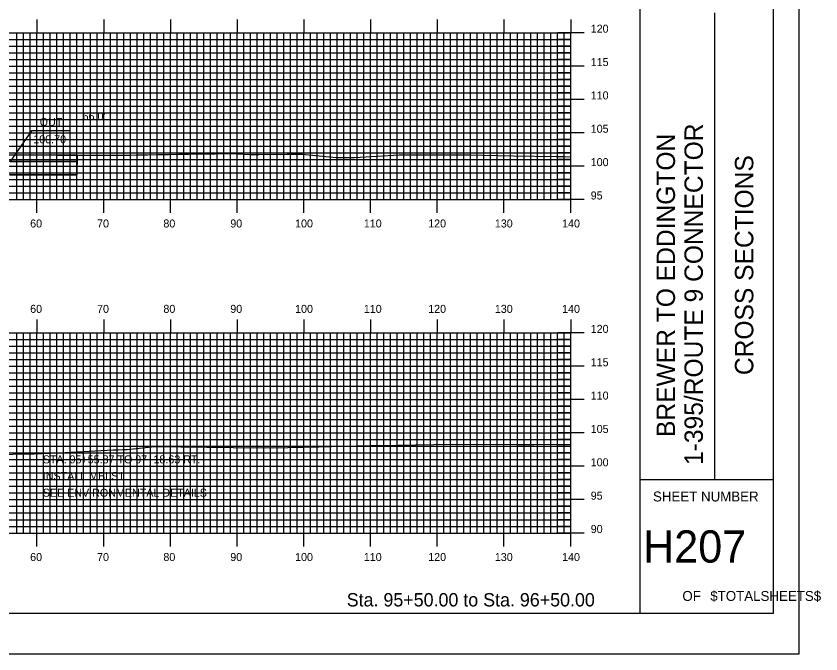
# Model space of a CAD drawing. Extents: x 1765726 to 1766069, y 442591 to 442811.
# Drawn here: x 1765948.8 to 1766069.4, y 442590.5 to 442686.2 of the extents above; entities that cross this region are included whole.
import ezdxf

# ---------------------------------------------------------------- set-up
doc = ezdxf.new("R2010")
doc.units = 0
for name, color, linetype in [('ANNOTATION', 7, 'Continuous'), ('BORDER', 7, 'Continuous'), ('D_Roadway_FinishedGrade', 7, 'Continuous'), ('D_Roadway_SlopeLines', 7, 'Continuous'), ('D_Text_Standard', 7, 'Continuous'), ('H_V ANNOTATION', 7, 'Continuous'), ('MAJOR', 7, 'Continuous'), ('MINOR', 7, 'Continuous'), ('PLOT BOUNDARY', 7, 'Continuous'), ('S_Roadway_Centerline', 7, 'Continuous')]:
    doc.layers.add(name, color=color, linetype=linetype)

msp = doc.modelspace()

# ---------------------------------------------------------------- linework, layer by layer
at = {"layer": 'ANNOTATION'}
msp.add_lwpolyline([(1765956.74, 442668.96), (1765951.05, 442668.96), (1765947.87, 442664.37)], dxfattribs=at)
at = {"layer": 'BORDER'}
for p, q in [((1766042.28, 442596.67), (1766042.28, 442806.67)), ((1766053.47, 442616.67), (1766053.47, 442686.67)), ((1766042.28, 442616.67), (1766062.28, 442616.67))]:
    msp.add_line(p, q, dxfattribs=at)
msp.add_lwpolyline([(1765742.28, 442596.67), (1766062.28, 442596.67), (1766062.28, 442806.67), (1765742.28, 442806.67)], close=True, dxfattribs=at)
at = {"layer": 'D_Roadway_FinishedGrade'}
for p, q in [((1765957.89, 442665.34), (1765957.88, 442662.37)), ((1765947.87, 442664.37), (1765957.88, 442664.37)), ((1765957.88, 442662.37), (1765947.87, 442662.37))]:
    msp.add_line(p, q, dxfattribs=at)
msp.add_lwpolyline([(1765931.99, 442670.4), (1765931.99, 442668.4), (1765947.87, 442662.37), (1765957.88, 442662.37), (1765957.88, 442664.37), (1765947.87, 442664.37)], close=True, dxfattribs=at)
at = {"layer": 'D_Roadway_SlopeLines'}
msp.add_lwpolyline([(1765947.88, 442665.37), (1765957.89, 442665.34)], dxfattribs=at)
at = {"layer": 'MAJOR'}
for p, q in [((1765951.88, 442685.67), (1765951.88, 442683.67)), ((1765961.88, 442685.67), (1765961.88, 442683.67)), ((1765971.88, 442685.67), (1765971.88, 442683.67)), ((1765981.88, 442685.67), (1765981.88, 442683.67)), ((1765991.88, 442685.67), (1765991.88, 442683.67)), ((1766001.88, 442685.67), (1766001.88, 442683.67)), ((1766011.88, 442685.67), (1766011.88, 442683.67)), ((1766021.88, 442685.67), (1766021.88, 442683.67)), ((1766031.88, 442685.67), (1766031.88, 442683.67)), ((1765751.88, 442683.67), (1766031.88, 442683.67)), ((1765751.88, 442683.67), (1766031.88, 442683.67)), ((1765951.88, 442658.67), (1765951.88, 442683.67)), ((1765961.88, 442658.67), (1765961.88, 442683.67)), ((1765971.88, 442658.67), (1765971.88, 442683.67)), ((1765981.88, 442658.67), (1765981.88, 442683.67)), ((1765991.88, 442658.67), (1765991.88, 442683.67)), ((1766001.88, 442658.67), (1766001.88, 442683.67)), ((1766011.88, 442658.67), (1766011.88, 442683.67)), ((1766021.88, 442658.67), (1766021.88, 442683.67)), ((1766033.89, 442683.67), (1766029.88, 442683.67)), ((1766031.88, 442658.67), (1766031.88, 442683.67)), ((1766031.88, 442658.67), (1766031.88, 442683.67)), ((1765751.88, 442678.67), (1766031.88, 442678.67)), ((1766033.89, 442678.67), (1766029.88, 442678.67)), ((1765751.88, 442673.67), (1766031.88, 442673.67)), ((1766033.89, 442673.67), (1766029.88, 442673.67)), ((1765751.88, 442668.67), (1766031.88, 442668.67)), ((1766033.89, 442668.67), (1766029.88, 442668.67)), ((1765751.88, 442663.67), (1766031.88, 442663.67)), ((1766033.89, 442663.67), (1766029.88, 442663.67)), ((1765751.88, 442658.67), (1766031.88, 442658.67)), ((1765751.88, 442658.67), (1766031.88, 442658.67)), ((1765951.88, 442656.66), (1765951.88, 442658.67)), ((1765961.88, 442656.66), (1765961.88, 442658.67)), ((1765971.88, 442656.66), (1765971.88, 442658.67)), ((1765981.88, 442656.66), (1765981.88, 442658.67)), ((1765991.88, 442656.66), (1765991.88, 442658.67)), ((1766001.88, 442656.66), (1766001.88, 442658.67)), ((1766011.88, 442656.66), (1766011.88, 442658.67)), ((1766021.88, 442656.66), (1766021.88, 442658.67)), ((1766033.89, 442658.67), (1766029.88, 442658.67)), ((1766031.88, 442656.66), (1766031.88, 442658.67)), ((1765951.88, 442640.67), (1765951.88, 442638.67)), ((1765961.88, 442640.67), (1765961.88, 442638.67)), ((1765971.88, 442640.67), (1765971.88, 442638.67)), ((1765981.88, 442640.67), (1765981.88, 442638.67)), ((1765991.88, 442640.67), (1765991.88, 442638.67)), ((1766001.88, 442640.67), (1766001.88, 442638.67)), ((1766011.88, 442640.67), (1766011.88, 442638.67)), ((1766021.88, 442640.67), (1766021.88, 442638.67)), ((1766031.88, 442640.67), (1766031.88, 442638.67)), ((1765751.88, 442638.67), (1766031.88, 442638.67)), ((1765751.88, 442638.67), (1766031.88, 442638.67)), ((1765951.88, 442608.67), (1765951.88, 442638.67)), ((1765961.88, 442608.67), (1765961.88, 442638.67)), ((1765971.88, 442608.67), (1765971.88, 442638.67)), ((1765981.88, 442608.67), (1765981.88, 442638.67)), ((1765991.88, 442608.67), (1765991.88, 442638.67)), ((1766001.88, 442608.67), (1766001.88, 442638.67)), ((1766011.88, 442608.67), (1766011.88, 442638.67)), ((1766021.88, 442608.67), (1766021.88, 442638.67)), ((1766033.89, 442638.67), (1766029.88, 442638.67)), ((1766031.88, 442608.67), (1766031.88, 442638.67)), ((1766031.88, 442608.67), (1766031.88, 442638.67)), ((1765751.88, 442633.67), (1766031.88, 442633.67)), ((1766033.89, 442633.67), (1766029.88, 442633.67)), ((1765751.88, 442628.67), (1766031.88, 442628.67)), ((1766033.89, 442628.67), (1766029.88, 442628.67)), ((1765751.88, 442623.67), (1766031.88, 442623.67)), ((1766033.89, 442623.67), (1766029.88, 442623.67)), ((1765751.88, 442618.67), (1766031.88, 442618.67)), ((1766033.89, 442618.67), (1766029.88, 442618.67)), ((1765751.88, 442613.67), (1766031.88, 442613.67)), ((1766033.89, 442613.67), (1766029.88, 442613.67)), ((1765751.88, 442608.67), (1766031.88, 442608.67)), ((1765751.88, 442608.67), (1766031.88, 442608.67)), ((1765951.88, 442606.66), (1765951.88, 442608.67)), ((1765961.88, 442606.66), (1765961.88, 442608.67)), ((1765971.88, 442606.66), (1765971.88, 442608.67)), ((1765981.88, 442606.66), (1765981.88, 442608.67)), ((1765991.88, 442606.66), (1765991.88, 442608.67)), ((1766001.88, 442606.66), (1766001.88, 442608.67)), ((1766011.88, 442606.66), (1766011.88, 442608.67)), ((1766021.88, 442606.66), (1766021.88, 442608.67)), ((1766033.89, 442608.67), (1766029.88, 442608.67)), ((1766031.88, 442606.66), (1766031.88, 442608.67))]:
    msp.add_line(p, q, dxfattribs=at)
at = {"layer": 'MINOR'}
for p, q in [((1765751.88, 442682.67), (1766031.88, 442682.67)), ((1765948.88, 442658.67), (1765948.88, 442683.67)), ((1765949.88, 442658.67), (1765949.88, 442683.67)), ((1765950.88, 442658.67), (1765950.88, 442683.67)), ((1765952.88, 442658.67), (1765952.88, 442683.67)), ((1765953.88, 442658.67), (1765953.88, 442683.67)), ((1765954.88, 442658.67), (1765954.88, 442683.67)), ((1765955.88, 442658.67), (1765955.88, 442683.67)), ((1765956.88, 442658.67), (1765956.88, 442683.67)), ((1765957.88, 442658.67), (1765957.88, 442683.67)), ((1765958.88, 442658.67), (1765958.88, 442683.67)), ((1765959.88, 442658.67), (1765959.88, 442683.67)), ((1765960.88, 442658.67), (1765960.88, 442683.67)), ((1765962.88, 442658.67), (1765962.88, 442683.67)), ((1765963.88, 442658.67), (1765963.88, 442683.67)), ((1765964.88, 442658.67), (1765964.88, 442683.67)), ((1765965.88, 442658.67), (1765965.88, 442683.67)), ((1765966.88, 442658.67), (1765966.88, 442683.67)), ((1765967.88, 442658.67), (1765967.88, 442683.67)), ((1765968.88, 442658.67), (1765968.88, 442683.67)), ((1765969.88, 442658.67), (1765969.88, 442683.67)), ((1765970.88, 442658.67), (1765970.88, 442683.67)), ((1765972.88, 442658.67), (1765972.88, 442683.67)), ((1765973.88, 442658.67), (1765973.88, 442683.67)), ((1765974.88, 442658.67), (1765974.88, 442683.67)), ((1765975.88, 442658.67), (1765975.88, 442683.67)), ((1765976.88, 442658.67), (1765976.88, 442683.67)), ((1765977.88, 442658.67), (1765977.88, 442683.67)), ((1765978.88, 442658.67), (1765978.88, 442683.67)), ((1765979.88, 442658.67), (1765979.88, 442683.67)), ((1765980.88, 442658.67), (1765980.88, 442683.67)), ((1765982.88, 442658.67), (1765982.88, 442683.67)), ((1765983.88, 442658.67), (1765983.88, 442683.67)), ((1765984.88, 442658.67), (1765984.88, 442683.67)), ((1765985.88, 442658.67), (1765985.88, 442683.67)), ((1765986.88, 442658.67), (1765986.88, 442683.67)), ((1765987.88, 442658.67), (1765987.88, 442683.67)), ((1765988.88, 442658.67), (1765988.88, 442683.67)), ((1765989.88, 442658.67), (1765989.88, 442683.67)), ((1765990.88, 442658.67), (1765990.88, 442683.67)), ((1765992.88, 442658.67), (1765992.88, 442683.67)), ((1765993.88, 442658.67), (1765993.88, 442683.67)), ((1765994.88, 442658.67), (1765994.88, 442683.67)), ((1765995.88, 442658.67), (1765995.88, 442683.67)), ((1765996.88, 442658.67), (1765996.88, 442683.67)), ((1765997.88, 442658.67), (1765997.88, 442683.67)), ((1765998.88, 442658.67), (1765998.88, 442683.67)), ((1765999.88, 442658.67), (1765999.88, 442683.67)), ((1766000.88, 442658.67), (1766000.88, 442683.67)), ((1766002.88, 442658.67), (1766002.88, 442683.67)), ((1766003.88, 442658.67), (1766003.88, 442683.67)), ((1766004.88, 442658.67), (1766004.88, 442683.67)), ((1766005.88, 442658.67), (1766005.88, 442683.67)), ((1766006.88, 442658.67), (1766006.88, 442683.67)), ((1766007.88, 442658.67), (1766007.88, 442683.67)), ((1766008.88, 442658.67), (1766008.88, 442683.67)), ((1766009.88, 442658.67), (1766009.88, 442683.67)), ((1766010.88, 442658.67), (1766010.88, 442683.67)), ((1766012.88, 442658.67), (1766012.88, 442683.67)), ((1766013.88, 442658.67), (1766013.88, 442683.67)), ((1766014.88, 442658.67), (1766014.88, 442683.67)), ((1766015.88, 442658.67), (1766015.88, 442683.67)), ((1766016.88, 442658.67), (1766016.88, 442683.67)), ((1766017.88, 442658.67), (1766017.88, 442683.67)), ((1766018.88, 442658.67), (1766018.88, 442683.67)), ((1766019.88, 442658.67), (1766019.88, 442683.67)), ((1766020.88, 442658.67), (1766020.88, 442683.67)), ((1766022.88, 442658.67), (1766022.88, 442683.67)), ((1766023.88, 442658.67), (1766023.88, 442683.67)), ((1766024.88, 442658.67), (1766024.88, 442683.67)), ((1766025.88, 442658.67), (1766025.88, 442683.67)), ((1766026.88, 442658.67), (1766026.88, 442683.67)), ((1766027.88, 442658.67), (1766027.88, 442683.67)), ((1766028.88, 442658.67), (1766028.88, 442683.67)), ((1766029.88, 442658.67), (1766029.88, 442683.67)), ((1766031.88, 442682.67), (1766029.88, 442682.67)), ((1766030.88, 442658.67), (1766030.88, 442683.67)), ((1765751.88, 442681.67), (1766031.88, 442681.67)), ((1766031.88, 442681.67), (1766029.88, 442681.67)), ((1765751.88, 442680.67), (1766031.88, 442680.67)), ((1766031.88, 442680.67), (1766029.88, 442680.67)), ((1765751.88, 442679.67), (1766031.88, 442679.67)), ((1766031.88, 442679.67), (1766029.88, 442679.67)), ((1765751.88, 442677.67), (1766031.88, 442677.67)), ((1765751.88, 442676.67), (1766031.88, 442676.67)), ((1766031.88, 442677.67), (1766029.88, 442677.67)), ((1766031.88, 442676.67), (1766029.88, 442676.67)), ((1765751.88, 442675.67), (1766031.88, 442675.67)), ((1766031.88, 442675.67), (1766029.88, 442675.67)), ((1765751.88, 442674.67), (1766031.88, 442674.67)), ((1766031.88, 442674.67), (1766029.88, 442674.67)), ((1765751.88, 442672.67), (1766031.88, 442672.67)), ((1766031.88, 442672.67), (1766029.88, 442672.67)), ((1765751.88, 442671.67), (1766031.88, 442671.67)), ((1765751.88, 442670.67), (1766031.88, 442670.67)), ((1766031.88, 442671.67), (1766029.88, 442671.67)), ((1766031.88, 442670.67), (1766029.88, 442670.67)), ((1765751.88, 442669.67), (1766031.88, 442669.67)), ((1766031.88, 442669.67), (1766029.88, 442669.67)), ((1765751.88, 442667.67), (1766031.88, 442667.67)), ((1766031.88, 442667.67), (1766029.88, 442667.67)), ((1765751.88, 442666.67), (1766031.88, 442666.67)), ((1766031.88, 442666.67), (1766029.88, 442666.67)), ((1765751.88, 442665.67), (1766031.88, 442665.67)), ((1765751.88, 442664.67), (1766031.88, 442664.67)), ((1766031.88, 442665.67), (1766029.88, 442665.67)), ((1766031.88, 442664.67), (1766029.88, 442664.67)), ((1765751.88, 442662.67), (1766031.88, 442662.67)), ((1766031.88, 442662.67), (1766029.88, 442662.67)), ((1765751.88, 442661.67), (1766031.88, 442661.67)), ((1766031.88, 442661.67), (1766029.88, 442661.67)), ((1765751.88, 442660.67), (1766031.88, 442660.67)), ((1766031.88, 442660.67), (1766029.88, 442660.67)), ((1765751.88, 442659.67), (1766031.88, 442659.67)), ((1766031.88, 442659.67), (1766029.88, 442659.67)), ((1765948.88, 442608.67), (1765948.88, 442638.67)), ((1765949.88, 442608.67), (1765949.88, 442638.67)), ((1765950.88, 442608.67), (1765950.88, 442638.67)), ((1765952.88, 442608.67), (1765952.88, 442638.67)), ((1765953.88, 442608.67), (1765953.88, 442638.67)), ((1765954.88, 442608.67), (1765954.88, 442638.67)), ((1765955.88, 442608.67), (1765955.88, 442638.67)), ((1765956.88, 442608.67), (1765956.88, 442638.67)), ((1765957.88, 442608.67), (1765957.88, 442638.67)), ((1765958.88, 442608.67), (1765958.88, 442638.67)), ((1765959.88, 442608.67), (1765959.88, 442638.67)), ((1765960.88, 442608.67), (1765960.88, 442638.67)), ((1765962.88, 442608.67), (1765962.88, 442638.67)), ((1765963.88, 442608.67), (1765963.88, 442638.67)), ((1765964.88, 442608.67), (1765964.88, 442638.67)), ((1765965.88, 442608.67), (1765965.88, 442638.67)), ((1765966.88, 442608.67), (1765966.88, 442638.67)), ((1765967.88, 442608.67), (1765967.88, 442638.67)), ((1765968.88, 442608.67), (1765968.88, 442638.67)), ((1765969.88, 442608.67), (1765969.88, 442638.67)), ((1765970.88, 442608.67), (1765970.88, 442638.67)), ((1765972.88, 442608.67), (1765972.88, 442638.67)), ((1765973.88, 442608.67), (1765973.88, 442638.67)), ((1765974.88, 442608.67), (1765974.88, 442638.67)), ((1765975.88, 442608.67), (1765975.88, 442638.67)), ((1765976.88, 442608.67), (1765976.88, 442638.67)), ((1765977.88, 442608.67), (1765977.88, 442638.67)), ((1765978.88, 442608.67), (1765978.88, 442638.67)), ((1765979.88, 442608.67), (1765979.88, 442638.67)), ((1765980.88, 442608.67), (1765980.88, 442638.67)), ((1765982.88, 442608.67), (1765982.88, 442638.67)), ((1765983.88, 442608.67), (1765983.88, 442638.67)), ((1765984.88, 442608.67), (1765984.88, 442638.67)), ((1765985.88, 442608.67), (1765985.88, 442638.67)), ((1765986.88, 442608.67), (1765986.88, 442638.67)), ((1765987.88, 442608.67), (1765987.88, 442638.67)), ((1765988.88, 442608.67), (1765988.88, 442638.67)), ((1765989.88, 442608.67), (1765989.88, 442638.67)), ((1765990.88, 442608.67), (1765990.88, 442638.67)), ((1765992.88, 442608.67), (1765992.88, 442638.67)), ((1765993.88, 442608.67), (1765993.88, 442638.67)), ((1765994.88, 442608.67), (1765994.88, 442638.67)), ((1765995.88, 442608.67), (1765995.88, 442638.67)), ((1765996.88, 442608.67), (1765996.88, 442638.67)), ((1765997.88, 442608.67), (1765997.88, 442638.67)), ((1765998.88, 442608.67), (1765998.88, 442638.67)), ((1765999.88, 442608.67), (1765999.88, 442638.67)), ((1766000.88, 442608.67), (1766000.88, 442638.67)), ((1766002.88, 442608.67), (1766002.88, 442638.67)), ((1766003.88, 442608.67), (1766003.88, 442638.67)), ((1766004.88, 442608.67), (1766004.88, 442638.67)), ((1766005.88, 442608.67), (1766005.88, 442638.67)), ((1766006.88, 442608.67), (1766006.88, 442638.67)), ((1766007.88, 442608.67), (1766007.88, 442638.67)), ((1766008.88, 442608.67), (1766008.88, 442638.67)), ((1766009.88, 442608.67), (1766009.88, 442638.67)), ((1766010.88, 442608.67), (1766010.88, 442638.67)), ((1766012.88, 442608.67), (1766012.88, 442638.67)), ((1766013.88, 442608.67), (1766013.88, 442638.67)), ((1766014.88, 442608.67), (1766014.88, 442638.67)), ((1766015.88, 442608.67), (1766015.88, 442638.67)), ((1766016.88, 442608.67), (1766016.88, 442638.67)), ((1766017.88, 442608.67), (1766017.88, 442638.67)), ((1766018.88, 442608.67), (1766018.88, 442638.67)), ((1766019.88, 442608.67), (1766019.88, 442638.67)), ((1766020.88, 442608.67), (1766020.88, 442638.67)), ((1766022.88, 442608.67), (1766022.88, 442638.67)), ((1766023.88, 442608.67), (1766023.88, 442638.67)), ((1766024.88, 442608.67), (1766024.88, 442638.67)), ((1766025.88, 442608.67), (1766025.88, 442638.67)), ((1766026.88, 442608.67), (1766026.88, 442638.67)), ((1766027.88, 442608.67), (1766027.88, 442638.67)), ((1766028.88, 442608.67), (1766028.88, 442638.67)), ((1766029.88, 442608.67), (1766029.88, 442638.67)), ((1766030.88, 442608.67), (1766030.88, 442638.67)), ((1765751.88, 442637.67), (1766031.88, 442637.67)), ((1766031.88, 442637.67), (1766029.88, 442637.67)), ((1765751.88, 442636.67), (1766031.88, 442636.67)), ((1765751.88, 442635.67), (1766031.88, 442635.67)), ((1766031.88, 442636.67), (1766029.88, 442636.67)), ((1766031.88, 442635.67), (1766029.88, 442635.67)), ((1765751.88, 442634.67), (1766031.88, 442634.67)), ((1766031.88, 442634.67), (1766029.88, 442634.67)), ((1765751.88, 442632.67), (1766031.88, 442632.67)), ((1766031.88, 442632.67), (1766029.88, 442632.67)), ((1765751.88, 442631.67), (1766031.88, 442631.67)), ((1766031.88, 442631.67), (1766029.88, 442631.67)), ((1765751.88, 442630.67), (1766031.88, 442630.67)), ((1765751.88, 442629.67), (1766031.88, 442629.67)), ((1766031.88, 442630.67), (1766029.88, 442630.67)), ((1766031.88, 442629.67), (1766029.88, 442629.67)), ((1765751.88, 442627.67), (1766031.88, 442627.67)), ((1766031.88, 442627.67), (1766029.88, 442627.67)), ((1765751.88, 442626.67), (1766031.88, 442626.67)), ((1766031.88, 442626.67), (1766029.88, 442626.67)), ((1765751.88, 442625.67), (1766031.88, 442625.67)), ((1766031.88, 442625.67), (1766029.88, 442625.67)), ((1765751.88, 442624.67), (1766031.88, 442624.67)), ((1766031.88, 442624.67), (1766029.88, 442624.67)), ((1765751.88, 442622.67), (1766031.88, 442622.67)), ((1766031.88, 442622.67), (1766029.88, 442622.67)), ((1765751.88, 442621.67), (1766031.88, 442621.67)), ((1766031.88, 442621.67), (1766029.88, 442621.67)), ((1765751.88, 442620.67), (1766031.88, 442620.67)), ((1766031.88, 442620.67), (1766029.88, 442620.67)), ((1765751.88, 442619.67), (1766031.88, 442619.67)), ((1766031.88, 442619.67), (1766029.88, 442619.67)), ((1765751.88, 442617.67), (1766031.88, 442617.67)), ((1766031.88, 442617.67), (1766029.88, 442617.67)), ((1765751.88, 442616.67), (1766031.88, 442616.67)), ((1766031.88, 442616.67), (1766029.88, 442616.67)), ((1765751.88, 442615.67), (1766031.88, 442615.67)), ((1766031.88, 442615.67), (1766029.88, 442615.67)), ((1765751.88, 442614.67), (1766031.88, 442614.67)), ((1766031.88, 442614.67), (1766029.88, 442614.67)), ((1765751.88, 442612.67), (1766031.88, 442612.67)), ((1765751.88, 442611.67), (1766031.88, 442611.67)), ((1766031.88, 442612.67), (1766029.88, 442612.67)), ((1766031.88, 442611.67), (1766029.88, 442611.67)), ((1765751.88, 442610.67), (1766031.88, 442610.67)), ((1766031.88, 442610.67), (1766029.88, 442610.67)), ((1765751.88, 442609.67), (1766031.88, 442609.67)), ((1766031.88, 442609.67), (1766029.88, 442609.67))]:
    msp.add_line(p, q, dxfattribs=at)
at = {"layer": 'PLOT BOUNDARY'}
msp.add_lwpolyline([(1765726.1, 442590.55), (1766066.1, 442590.55), (1766066.1, 442810.55), (1765726.1, 442810.55)], close=True, dxfattribs=at)
at = {"layer": 'S_Roadway_Centerline'}
for points in [[(1765947.5, 442665.37), (1765949.37, 442665.36), (1765951.1, 442665.36), (1765952.29, 442665.35), (1765953.59, 442665.34), (1765954.99, 442665.33), (1765955.53, 442665.31), (1765956.81, 442665.3), (1765958.16, 442665.3), (1765959.58, 442665.29), (1765960.17, 442665.29), (1765961, 442665.29), (1765961.05, 442665.29), (1765962.52, 442665.29), (1765963.91, 442665.29), (1765965.21, 442665.29), (1765965.74, 442665.33), (1765967.01, 442665.35), (1765968.49, 442665.37), (1765970.04, 442665.39), (1765971.61, 442665.41), (1765973.15, 442665.44), (1765974.64, 442665.46), (1765977.38, 442665.51), (1765978.6, 442665.53), (1765979.72, 442665.55), (1765980.74, 442665.56), (1765983.83, 442665.42), (1765985.12, 442665.43), (1765989.37, 442665.46), (1765991.64, 442665.48), (1765996.72, 442664.98), (1765999.49, 442664.94), (1766006.18, 442665.37), (1766008.18, 442665.37), (1766010.04, 442665.37), (1766011.75, 442665.37), (1766013.29, 442665.37), (1766014.97, 442665.36), (1766016.77, 442665.35), (1766018.65, 442665.33), (1766023.29, 442665.19), (1766029.73, 442665.1), (1766030.94, 442665.09), (1766031.88, 442665.08)], [(1765945.08, 442620.46), (1765951.48, 442620.56), (1765956.1, 442620.72), (1765963.28, 442621.13), (1765964.04, 442621.16), (1765964.75, 442621.19), (1765965.4, 442621.21), (1765969.48, 442621.62), (1765981.3, 442621.47), (1765987.19, 442621.44), (1765994.13, 442621.58), (1766001.79, 442621.77), (1766005.81, 442621.84), (1766014.17, 442621.98), (1766023.8, 442621.94), (1766026.37, 442621.94), (1766031.88, 442621.98)]]:
    msp.add_lwpolyline(points, dxfattribs=at)

# ---------------------------------------------------------------- texts
at = {"layer": 'ANNOTATION'}
for s, p in [('OUT', (1765952.29, 442669.69)), ('100.70', (1765951.33, 442667.09))]:
    msp.add_text(s, height=1.2, dxfattribs=at).set_placement(p)
at = {"layer": 'BORDER'}
for s, p in [('1-395/ROUTE 9 CONNECTOR', (1766051.69, 442618.87)), ('BREWER TO EDDINGTON', (1766047.51, 442623.07)), ('CROSS SECTIONS', (1766059.25, 442632.34))]:
    msp.add_text(s, height=2.7557, rotation=90, dxfattribs=at).set_placement(p)
for s, height, p in [('SHEET NUMBER', 1.4905, (1766044.21, 442613.4)), ('H207', 4.839, (1766042.72, 442604.23)), ('OF', 1.491, (1766048.62, 442598.49)), ('$TOTALSHEETS$', 1.4905, (1766052.8, 442598.49))]:
    msp.add_text(s, height=height, dxfattribs=at).set_placement(p)
at = {"layer": 'D_Text_Standard'}
for s, p in [("66.0'", (1765958.72, 442670.54)), ('STA. 95+55.87 TO 97+18.63 RT.', (1765952.75, 442619.11)), ('INSTALL MBLS1', (1765952.75, 442616.61)), ('SEE ENVIRONMENTAL DETAILS', (1765952.75, 442614.11))]:
    msp.add_text(s, height=1.2, dxfattribs=at).set_placement(p)
at = {"layer": 'H_V ANNOTATION'}
for s, height, p in [('120', 1.2, (1766034.88, 442683.67)), ('115', 1.2, (1766034.88, 442678.67)), ('110', 1.2, (1766034.88, 442673.67)), ('105', 1.2, (1766034.88, 442668.67)), ('100', 1.2, (1766034.88, 442663.67)), ('95', 1.2, (1766034.88, 442658.67)), ('60', 1.2, (1765950.86, 442654.47)), ('70', 1.2, (1765960.89, 442654.47)), ('80', 1.2, (1765970.83, 442654.47)), ('90', 1.2, (1765980.86, 442654.47)), ('100', 1.2, (1765990.57, 442654.47)), ('110', 1.2, (1766000.87, 442654.47)), ('120', 1.2, (1766010.52, 442654.47)), ('130', 1.2, (1766020.51, 442654.47)), ('140', 1.2, (1766030.59, 442654.47)), ('60', 1.2, (1765950.86, 442641.67)), ('70', 1.2, (1765960.89, 442641.67)), ('80', 1.2, (1765970.83, 442641.67)), ('90', 1.2, (1765980.86, 442641.67)), ('100', 1.2, (1765990.57, 442641.67)), ('110', 1.2, (1766000.87, 442641.67)), ('120', 1.2, (1766010.52, 442641.67)), ('130', 1.2, (1766020.51, 442641.67)), ('140', 1.2, (1766030.59, 442641.67)), ('120', 1.2, (1766034.88, 442638.67)), ('115', 1.2, (1766034.88, 442633.67)), ('110', 1.2, (1766034.88, 442628.67)), ('105', 1.2, (1766034.88, 442623.67)), ('100', 1.2, (1766034.88, 442618.67)), ('95', 1.2, (1766034.88, 442613.67)), ('90', 1.2, (1766034.88, 442608.67)), ('60', 1.2, (1765950.86, 442604.47)), ('70', 1.2, (1765960.89, 442604.47)), ('80', 1.2, (1765970.83, 442604.47)), ('90', 1.2, (1765980.86, 442604.47)), ('100', 1.2, (1765990.57, 442604.47)), ('110', 1.2, (1766000.87, 442604.47)), ('120', 1.2, (1766010.52, 442604.47)), ('130', 1.2, (1766020.51, 442604.47)), ('140', 1.2, (1766030.59, 442604.47)), ('Sta. 95+50.00 to Sta. 96+50.00', 2.0004, (1765998.31, 442597.66))]:
    msp.add_text(s, height=height, dxfattribs=at).set_placement(p)

doc.saveas('drawing.dxf')
